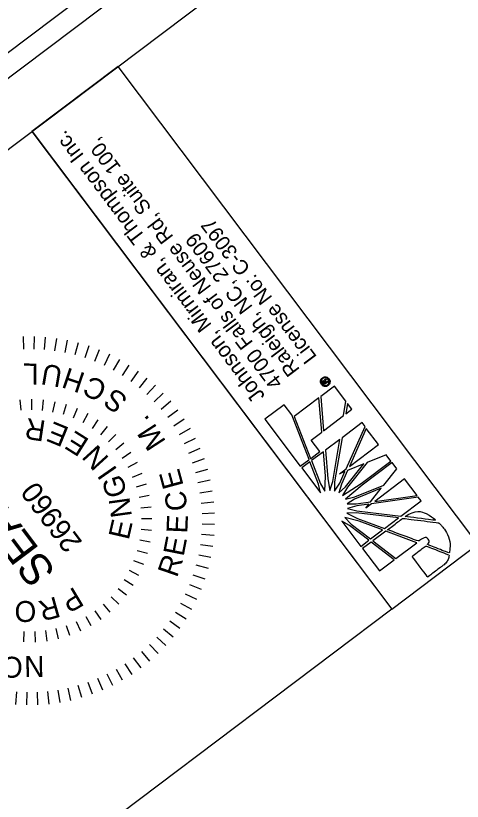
# Model space of a CAD drawing. Extents: x 1263113 to 1265001, y 775064 to 777068.
# Drawn here: x 1263247.8 to 1263346, y 776344.6 to 776517.2 of the extents above; entities that cross this region are included whole.
import ezdxf

# ---------------------------------------------------------------- set-up
doc = ezdxf.new("R2010")
doc.units = 0
for name, color, linetype in [('Default', 7, 'Continuous'), ('Sheet Data Field CELL', 7, 'Continuous'), ('Sheet Plan CELL', 7, 'Continuous'), ('Sheet Plot Border Inside CELL', 7, 'Continuous'), ('Sheet Plot Border Outside CELL', 7, 'Continuous'), ('Sheet Typical CELL', 7, 'Continuous')]:
    doc.layers.add(name, color=color, linetype=linetype)

msp = doc.modelspace()

# ---------------------------------------------------------------- linework, layer by layer
at = {"layer": 'Default'}
for p, q in [((1263249.42, 776446.7), (1263249.53, 776443.95)), ((1263251.87, 776446.73), (1263251.81, 776443.97)), ((1263254.31, 776446.61), (1263254.09, 776443.86)), ((1263256.74, 776446.33), (1263256.35, 776443.6)), ((1263259.15, 776445.92), (1263258.6, 776443.22)), ((1263261.53, 776445.36), (1263260.82, 776442.69)), ((1263263.87, 776444.66), (1263263, 776442.04)), ((1263266.17, 776443.81), (1263265.14, 776441.25)), ((1263268.41, 776442.83), (1263267.23, 776440.34)), ((1263270.59, 776441.71), (1263269.25, 776439.3)), ((1263272.7, 776440.47), (1263271.22, 776438.14)), ((1263274.72, 776439.11), (1263273.1, 776436.86)), ((1263276.66, 776437.61), (1263274.92, 776435.48)), ((1263278.51, 776436.01), (1263276.64, 776433.99)), ((1263280.25, 776434.3), (1263278.26, 776432.39)), ((1263248.69, 776432.83), (1263248.9, 776430.54)), ((1263251.27, 776432.93), (1263251.25, 776430.63)), ((1263253.84, 776432.79), (1263253.61, 776430.5)), ((1263256.39, 776432.4), (1263255.93, 776430.14)), ((1263281.89, 776432.49), (1263279.79, 776430.7)), ((1263258.89, 776431.76), (1263258.22, 776429.56)), ((1263261.32, 776430.88), (1263260.43, 776428.76)), ((1263283.42, 776430.58), (1263281.22, 776428.92)), ((1263263.65, 776429.78), (1263262.56, 776427.75)), ((1263265.86, 776428.45), (1263264.58, 776426.54)), ((1263284.83, 776428.58), (1263282.53, 776427.06)), ((1263267.93, 776426.92), (1263266.48, 776425.14)), ((1263286.12, 776426.5), (1263283.73, 776425.12)), ((1263269.85, 776425.2), (1263268.23, 776423.56)), ((1263287.28, 776424.35), (1263284.81, 776423.11)), ((1263271.59, 776423.3), (1263269.82, 776421.83)), ((1263288.31, 776422.13), (1263285.77, 776421.04)), ((1263273.14, 776421.24), (1263271.24, 776419.94)), ((1263274.48, 776419.03), (1263272.47, 776417.93)), ((1263289.2, 776419.85), (1263286.6, 776418.92)), ((1263273.5, 776415.8), (1263275.62, 776416.7)), ((1263289.95, 776417.52), (1263287.3, 776416.75)), ((1263290.55, 776415.15), (1263287.87, 776414.54)), ((1263276.5, 776414.3), (1263274.31, 776413.6)), ((1263277.16, 776411.8), (1263274.91, 776411.32)), ((1263291.02, 776412.75), (1263288.3, 776412.31)), ((1263291.34, 776410.32), (1263288.6, 776410.05)), ((1263277.58, 776409.25), (1263275.29, 776409)), ((1263277.74, 776406.68), (1263275.44, 776406.64)), ((1263291.52, 776407.89), (1263288.76, 776407.78)), ((1263291.54, 776405.44), (1263288.78, 776405.5)), ((1263277.66, 776404.1), (1263275.37, 776404.29)), ((1263291.42, 776403), (1263288.67, 776403.22)), ((1263277.33, 776401.55), (1263275.07, 776401.95)), ((1263276.75, 776399.04), (1263274.54, 776399.66)), ((1263291.15, 776400.57), (1263288.42, 776400.95)), ((1263290.73, 776398.16), (1263288.03, 776398.71)), ((1263275.94, 776396.59), (1263273.79, 776397.42)), ((1263290.17, 776395.77), (1263287.51, 776396.49)), ((1263274.89, 776394.24), (1263272.83, 776395.27)), ((1263289.47, 776393.43), (1263286.85, 776394.31)), ((1263273.62, 776391.99), (1263271.68, 776393.22)), ((1263272.14, 776389.88), (1263270.32, 776391.29)), ((1263288.63, 776391.14), (1263286.06, 776392.17)), ((1263270.46, 776387.92), (1263268.79, 776389.5)), ((1263287.64, 776388.9), (1263285.15, 776390.08)), ((1263268.6, 776386.13), (1263267.09, 776387.87)), ((1263286.53, 776386.72), (1263284.11, 776388.05)), ((1263266.58, 776384.54), (1263265.24, 776386.41)), ((1263285.29, 776384.61), (1263282.95, 776386.09)), ((1263262.11, 776381.96), (1263261.16, 776384.05)), ((1263264.41, 776383.14), (1263263.26, 776385.13)), ((1263283.92, 776382.59), (1263281.68, 776384.2)), ((1263257.24, 776380.29), (1263256.71, 776382.53)), ((1263259.72, 776381.01), (1263258.97, 776383.18)), ((1263282.43, 776380.65), (1263280.29, 776382.39)), ((1263249.56, 776379.61), (1263249.69, 776381.9)), ((1263252.14, 776379.58), (1263252.05, 776381.88)), ((1263254.7, 776379.81), (1263254.4, 776382.09)), ((1263280.83, 776378.8), (1263278.8, 776380.67)), ((1263279.11, 776377.05), (1263277.2, 776379.04)), ((1263277.3, 776375.41), (1263275.51, 776377.52)), ((1263275.39, 776373.88), (1263273.73, 776376.09)), ((1263271.31, 776371.19), (1263269.93, 776373.58)), ((1263273.39, 776372.47), (1263271.87, 776374.77)), ((1263269.16, 776370.03), (1263267.92, 776372.5)), ((1263264.66, 776368.11), (1263263.73, 776370.71)), ((1263266.94, 776369), (1263265.85, 776371.54)), ((1263247.81, 776365.89), (1263248.03, 776368.64)), ((1263250.26, 776365.77), (1263250.31, 776368.53)), ((1263252.7, 776365.79), (1263252.59, 776368.55)), ((1263255.14, 776365.96), (1263254.86, 776368.71)), ((1263257.56, 776366.28), (1263257.12, 776369.01)), ((1263259.96, 776366.75), (1263259.36, 776369.44)), ((1263262.33, 776367.36), (1263261.57, 776370.01))]:
    msp.add_line(p, q, dxfattribs=at)
at = {"layer": 'Sheet Data Field CELL'}
for p, q in [((1263316.52, 776437.3), (1263316.68, 776437.43)), ((1263316.68, 776437.43), (1263316.52, 776437.3)), ((1263316.68, 776437.43), (1263316.68, 776437.43)), ((1263317.89, 776435.83), (1263314.85, 776433.53)), ((1263315.03, 776436.18), (1263315.19, 776436.3)), ((1263315.19, 776436.3), (1263315.03, 776436.18)), ((1263315.47, 776436.52), (1263315.44, 776436.56)), ((1263315.47, 776436.52), (1263315.62, 776436.62)), ((1263315.62, 776436.62), (1263315.47, 776436.52)), ((1263315.7, 776436.21), (1263315.47, 776436.52)), ((1263315.6, 776436.64), (1263315.62, 776436.62)), ((1263315.62, 776436.62), (1263315.72, 776436.49)), ((1263316.46, 776436.78), (1263315.7, 776436.21)), ((1263315.72, 776436.49), (1263315.9, 776436.62)), ((1263315.79, 776436.76), (1263315.93, 776436.86)), ((1263315.93, 776436.86), (1263315.79, 776436.76)), ((1263315.79, 776436.76), (1263315.79, 776436.77)), ((1263315.9, 776436.62), (1263315.79, 776436.76)), ((1263315.93, 776436.87), (1263315.93, 776436.86)), ((1263315.93, 776436.86), (1263316.03, 776436.72)), ((1263316.03, 776436.72), (1263316.33, 776436.95)), ((1263316.33, 776436.95), (1263316.46, 776436.78)), ((1263316.52, 776437.3), (1263316.51, 776437.31)), ((1263320.41, 776432.5), (1263317.89, 776435.83)), ((1263314.47, 776433.25), (1263309.05, 776429.16)), ((1263315.08, 776425.73), (1263314.47, 776433.25)), ((1263314.85, 776433.53), (1263315.49, 776426.03)), ((1263319.88, 776429.34), (1263320.41, 776432.5)), ((1263306.81, 776431.73), (1263302.58, 776428.54)), ((1263308.47, 776429.53), (1263306.81, 776431.73)), ((1263320.77, 776432.02), (1263320.36, 776429.71)), ((1263320.36, 776429.71), (1263321.73, 776430.75)), ((1263321.73, 776430.75), (1263320.77, 776432.02)), ((1263312.33, 776419.69), (1263308.47, 776429.53)), ((1263309.05, 776429.16), (1263312.62, 776419.91)), ((1263315.49, 776426.03), (1263319.88, 776429.34)), ((1263302.58, 776428.54), (1263310.37, 776418.22)), ((1263323.95, 776427.81), (1263319.54, 776424.49)), ((1263324.6, 776426.95), (1263323.95, 776427.81)), ((1263312.73, 776423.95), (1263315.08, 776425.73)), ((1263320.45, 776417.66), (1263324.6, 776426.95)), ((1263324.88, 776426.52), (1263321.15, 776418.19)), ((1263327.54, 776423.01), (1263324.88, 776426.52)), ((1263314.63, 776421.43), (1263312.73, 776423.95)), ((1263319.03, 776424.1), (1263315.89, 776421.73)), ((1263317.51, 776414.84), (1263319.03, 776424.1)), ((1263319.54, 776424.49), (1263317.92, 776414.81)), ((1263321.15, 776418.19), (1263327.54, 776423.01)), ((1263312.65, 776419.93), (1263314.63, 776421.43)), ((1263315.45, 776421.4), (1263312.82, 776419.47)), ((1263315.92, 776416.06), (1263315.45, 776421.4)), ((1263315.89, 776421.73), (1263316.39, 776415.48)), ((1263329.25, 776420.73), (1263325.08, 776419.07)), ((1263330.28, 776419.37), (1263329.25, 776420.73)), ((1263310.37, 776418.22), (1263312.27, 776419.65)), ((1263312.45, 776419.19), (1263310.69, 776417.85)), ((1263312.27, 776419.65), (1263312.33, 776419.69)), ((1263314.38, 776414.26), (1263312.45, 776419.19)), ((1263312.62, 776419.91), (1263312.65, 776419.93)), ((1263312.82, 776419.47), (1263314.84, 776414.39)), ((1263320.31, 776413.73), (1263324.31, 776418.74)), ((1263324.31, 776418.74), (1263320.74, 776417.28)), ((1263325.08, 776419.07), (1263320.76, 776413.59)), ((1263323.74, 776414.43), (1263330.28, 776419.37)), ((1263330.54, 776419.02), (1263324, 776414.08)), ((1263331.56, 776417.68), (1263330.54, 776419.02)), ((1263310.69, 776417.85), (1263314.77, 776412.39)), ((1263319.01, 776416.57), (1263320.45, 776417.66)), ((1263320.18, 776417.06), (1263319.01, 776416.57)), ((1263319.02, 776414.53), (1263320.18, 776417.06)), ((1263320.74, 776417.28), (1263319.39, 776414.27)), ((1263328.72, 776414.08), (1263331.56, 776417.68)), ((1263315.79, 776412.73), (1263315.92, 776416.06)), ((1263316.39, 776415.48), (1263316.87, 776412.87)), ((1263333.26, 776415.47), (1263326.74, 776410.5)), ((1263336.02, 776411.81), (1263333.26, 776415.47)), ((1263314.77, 776412.39), (1263314.38, 776414.26)), ((1263314.84, 776414.39), (1263315.79, 776412.73)), ((1263316.87, 776412.87), (1263317.51, 776414.84)), ((1263317.92, 776414.81), (1263317.9, 776412.74)), ((1263317.9, 776412.74), (1263319.02, 776414.53)), ((1263319.39, 776414.27), (1263318.86, 776412.38)), ((1263318.86, 776412.38), (1263320.31, 776413.73)), ((1263319.67, 776411.76), (1263323.74, 776414.43)), ((1263320.76, 776413.59), (1263319.67, 776411.76)), ((1263324, 776414.08), (1263320.29, 776410.95)), ((1263328.16, 776413.4), (1263322.3, 776410.98)), ((1263322.36, 776411.46), (1263328.72, 776414.08)), ((1263325.8, 776410.39), (1263328.16, 776413.4)), ((1263326.74, 776410.5), (1263336.02, 776411.81)), ((1263320.29, 776410.95), (1263322.36, 776411.46)), ((1263322.3, 776410.98), (1263320.68, 776409.97)), ((1263320.68, 776409.97), (1263322.66, 776409.94)), ((1263322.66, 776409.94), (1263325.8, 776410.39)), ((1263325.44, 776409.91), (1263322.8, 776409.52)), ((1263326.03, 776409.97), (1263324.74, 776408.99)), ((1263324.74, 776408.99), (1263325.44, 776409.91)), ((1263336.31, 776411.43), (1263326.03, 776409.97)), ((1263332.47, 776407.26), (1263336.92, 776410.62)), ((1263336.92, 776410.62), (1263336.31, 776411.43)), ((1263322.8, 776409.52), (1263320.77, 776408.94)), ((1263320.77, 776408.94), (1263322.76, 776408.39)), ((1263322.76, 776408.39), (1263332.47, 776407.26)), ((1263323.34, 776406.16), (1263320.15, 776406.94)), ((1263320.15, 776406.94), (1263321.56, 776405.49)), ((1263322.65, 776407.98), (1263320.61, 776407.92)), ((1263320.61, 776407.92), (1263322.97, 776406.77)), ((1263331.95, 776406.87), (1263322.65, 776407.98)), ((1263322.97, 776406.77), (1263328.89, 776404.56)), ((1263328.89, 776404.56), (1263331.95, 776406.87)), ((1263321.18, 776405.2), (1263319.49, 776406.14)), ((1263319.49, 776406.14), (1263323.66, 776400.61)), ((1263325.42, 776401.94), (1263321.18, 776405.2)), ((1263321.56, 776405.49), (1263325.8, 776402.23)), ((1263328.46, 776404.23), (1263323.34, 776406.16)), ((1263325.8, 776402.23), (1263328.46, 776404.23)), ((1263329.16, 776403.97), (1263326.32, 776401.82)), ((1263335.98, 776401.4), (1263329.16, 776403.97)), ((1263323.66, 776400.61), (1263325.42, 776401.94)), ((1263325.96, 776401.55), (1263324.07, 776400.12)), ((1263331.03, 776397.67), (1263325.96, 776401.55)), ((1263326.32, 776401.82), (1263331.4, 776397.95)), ((1263331.4, 776397.95), (1263335.98, 776401.4)), ((1263324.07, 776400.12), (1263327.77, 776395.21)), ((1263327.77, 776395.21), (1263331.03, 776397.67))]:
    msp.add_line(p, q, dxfattribs=at)
msp.add_lwpolyline([(1263349.4, 776401.09), (1263270.32, 776506.07), (1263251.38, 776491.8), (1263330.45, 776386.82)], close=True, dxfattribs=at)
for points in [[(1263315.8, 776437.28), (1263315.84, 776437.31), (1263315.86, 776437.33), (1263315.89, 776437.36), (1263315.96, 776437.44), (1263316.07, 776437.28)], [(1263315.49, 776426.03), (1263319.88, 776429.34), (1263320.41, 776432.5), (1263317.89, 776435.83), (1263314.85, 776433.53), (1263315.49, 776426.03), (1263315.49, 776426.03)], [(1263312.62, 776419.91), (1263312.65, 776419.93), (1263314.63, 776421.43), (1263312.73, 776423.95), (1263315.08, 776425.73), (1263314.47, 776433.25), (1263309.05, 776429.16), (1263312.62, 776419.91)], [(1263302.58, 776428.54), (1263310.37, 776418.22), (1263312.27, 776419.65), (1263312.33, 776419.69), (1263308.47, 776429.53), (1263306.81, 776431.73), (1263302.58, 776428.54)], [(1263321.73, 776430.75), (1263321.73, 776430.75), (1263320.77, 776432.02), (1263320.36, 776429.71), (1263321.73, 776430.75)], [(1263317.9, 776412.74), (1263319.02, 776414.53), (1263320.18, 776417.06), (1263319.01, 776416.57), (1263320.45, 776417.66), (1263324.6, 776426.95), (1263323.95, 776427.81), (1263319.54, 776424.49), (1263317.92, 776414.81), (1263317.9, 776412.74)], [(1263327.54, 776423.01), (1263324.88, 776426.52), (1263321.15, 776418.19), (1263327.54, 776423.01)], [(1263316.87, 776412.87), (1263317.51, 776414.84), (1263319.03, 776424.1), (1263315.89, 776421.73), (1263316.39, 776415.48), (1263316.87, 776412.87)], [(1263315.79, 776412.73), (1263315.92, 776416.06), (1263315.45, 776421.4), (1263312.82, 776419.47), (1263314.84, 776414.39), (1263315.79, 776412.73)], [(1263319.67, 776411.76), (1263323.74, 776414.43), (1263330.28, 776419.37), (1263329.25, 776420.73), (1263325.08, 776419.07), (1263320.76, 776413.59), (1263319.67, 776411.76)], [(1263314.38, 776414.26), (1263312.45, 776419.19), (1263310.69, 776417.85), (1263314.77, 776412.39), (1263314.38, 776414.26)], [(1263318.86, 776412.38), (1263320.31, 776413.73), (1263324.31, 776418.74), (1263320.74, 776417.28), (1263319.39, 776414.27), (1263318.86, 776412.38)], [(1263322.36, 776411.46), (1263328.72, 776414.08), (1263331.56, 776417.68), (1263330.54, 776419.02), (1263324, 776414.08), (1263320.29, 776410.95), (1263322.36, 776411.46)], [(1263336.02, 776411.81), (1263333.26, 776415.47), (1263326.74, 776410.5), (1263336.02, 776411.81)], [(1263320.68, 776409.97), (1263322.66, 776409.94), (1263325.8, 776410.39), (1263328.16, 776413.4), (1263322.3, 776410.98), (1263320.68, 776409.97)], [(1263320.77, 776408.94), (1263322.76, 776408.39), (1263332.47, 776407.26), (1263336.92, 776410.62), (1263336.31, 776411.43), (1263326.03, 776409.97), (1263324.74, 776408.99), (1263325.44, 776409.91), (1263322.8, 776409.52), (1263320.77, 776408.94)], [(1263325.8, 776402.23), (1263328.46, 776404.23), (1263323.34, 776406.16), (1263320.15, 776406.94), (1263321.56, 776405.49), (1263325.8, 776402.23)], [(1263328.89, 776404.56), (1263331.95, 776406.87), (1263322.65, 776407.98), (1263320.61, 776407.92), (1263322.97, 776406.77), (1263328.89, 776404.56)], [(1263321.18, 776405.2), (1263319.49, 776406.14), (1263323.66, 776400.61), (1263325.42, 776401.94), (1263321.18, 776405.2)], [(1263335.98, 776401.4), (1263329.16, 776403.97), (1263326.32, 776401.82), (1263331.4, 776397.95), (1263335.98, 776401.4)], [(1263331.03, 776397.67), (1263325.96, 776401.55), (1263324.07, 776400.12), (1263327.77, 776395.21), (1263331.03, 776397.67)]]:
    msp.add_lwpolyline(points, dxfattribs=at)
for points, degree in [([(1263315.03, 776436.18), (1263314.85, 776436.41), (1263314.79, 776436.67), (1263314.82, 776436.96), (1263314.85, 776437.23), (1263314.98, 776437.46), (1263315.21, 776437.64)], 3), ([(1263316.51, 776437.31), (1263316.37, 776437.5), (1263316.19, 776437.61), (1263315.97, 776437.64), (1263315.74, 776437.67), (1263315.52, 776437.61), (1263315.34, 776437.48), (1263315.15, 776437.34), (1263315.04, 776437.14), (1263315.01, 776436.92), (1263314.99, 776436.69), (1263315.04, 776436.49), (1263315.19, 776436.3)], 3), ([(1263316.68, 776437.43), (1263316.85, 776437.2), (1263316.92, 776436.94), (1263316.88, 776436.66), (1263316.84, 776436.37), (1263316.71, 776436.14), (1263316.48, 776435.97), (1263316.24, 776435.79), (1263315.98, 776435.72), (1263315.71, 776435.78), (1263315.43, 776435.82), (1263315.2, 776435.95), (1263315.03, 776436.18)], 3), ([(1263315.21, 776437.64), (1263315.45, 776437.81), (1263315.71, 776437.88), (1263315.99, 776437.85), (1263316.27, 776437.8), (1263316.5, 776437.67), (1263316.68, 776437.43)], 3), ([(1263315.19, 776436.3), (1263315.33, 776436.12), (1263315.51, 776436.01), (1263315.73, 776435.97), (1263315.95, 776435.94), (1263316.17, 776435.99), (1263316.35, 776436.13), (1263316.54, 776436.27), (1263316.65, 776436.46), (1263316.68, 776436.69), (1263316.71, 776436.92), (1263316.66, 776437.12), (1263316.52, 776437.3)], 3), ([(1263315.44, 776436.56), (1263315.29, 776436.76), (1263315.3, 776436.91), (1263315.45, 776437.02), (1263315.51, 776437.07), (1263315.59, 776437.09), (1263315.68, 776437.06)], 3), ([(1263315.79, 776436.77), (1263315.71, 776436.87), (1263315.63, 776436.9), (1263315.57, 776436.86), (1263315.51, 776436.82), (1263315.52, 776436.75), (1263315.6, 776436.64)], 3), ([(1263315.68, 776437.06), (1263315.67, 776437.12), (1263315.71, 776437.2), (1263315.8, 776437.28)], 2), ([(1263316.07, 776437.28), (1263316.05, 776437.23), (1263316.02, 776437.18), (1263315.96, 776437.14), (1263315.9, 776437.09), (1263315.86, 776437.05), (1263315.85, 776437.02)], 3), ([(1263315.85, 776437.02), (1263315.86, 776436.99), (1263315.87, 776436.94), (1263315.93, 776436.87)], 2), ([(1263333.39, 776407.16), (1263333.39, 776407.16), (1263340.23, 776406.31), (1263340.23, 776406.31), (1263338.35, 776407.83), (1263335.71, 776408.76), (1263333.39, 776407.16)], 3), ([(1263338.5, 776402.2), (1263338.72, 776401.91), (1263338.75, 776401.53), (1263338.28, 776401.02), (1263338.28, 776401.02), (1263343.12, 776399.14), (1263343.12, 776399.14), (1263343.44, 776401.09), (1263342.82, 776403.33), (1263341.71, 776404.8), (1263341.42, 776405.18), (1263341.17, 776405.45), (1263340.78, 776405.79), (1263340.78, 776405.79), (1263332.88, 776406.77), (1263332.88, 776406.77), (1263332.88, 776406.77), (1263329.57, 776404.27), (1263329.57, 776404.27), (1263329.57, 776404.27), (1263336.39, 776401.72), (1263336.39, 776401.72), (1263337.63, 776402.65), (1263338.19, 776402.6), (1263338.5, 776402.2)], 3), ([(1263338.5, 776402.2), (1263338.72, 776401.91), (1263338.75, 776401.53), (1263338.28, 776401.02), (1263338.28, 776401.02), (1263343.12, 776399.14), (1263343.12, 776399.14), (1263343.44, 776401.09), (1263342.82, 776403.33), (1263341.71, 776404.8), (1263341.42, 776405.18), (1263341.17, 776405.45), (1263340.78, 776405.79), (1263340.78, 776405.79), (1263332.88, 776406.77), (1263332.88, 776406.77), (1263332.88, 776406.77), (1263329.57, 776404.27), (1263329.57, 776404.27), (1263329.57, 776404.27), (1263336.39, 776401.72), (1263336.39, 776401.72), (1263337.63, 776402.65), (1263338.19, 776402.6), (1263338.5, 776402.2)], 3), ([(1263334.94, 776398.41), (1263334.94, 776398.41), (1263338.37, 776393.86), (1263338.37, 776393.86), (1263338.37, 776393.86), (1263341.21, 776396.01), (1263341.21, 776396.01), (1263341.21, 776396.01), (1263341.51, 776396.23), (1263341.51, 776396.23), (1263342.4, 776396.91), (1263342.89, 776397.73), (1263343.09, 776398.69), (1263343.09, 776398.69), (1263338, 776400.72), (1263337.94, 776400.67), (1263337.94, 776400.67), (1263334.94, 776398.41), (1263334.94, 776398.41)], 3)]:
    msp.add_open_spline(points, degree=degree, dxfattribs=at)
at = {"layer": 'Sheet Plan CELL'}
msp.add_lwpolyline([(1263251.41, 776491.76), (1263330.45, 776386.82), (1263240.62, 776319.15), (1263161.57, 776424.1)], dxfattribs=at)
at = {"layer": 'Sheet Plot Border Inside CELL'}
msp.add_lwpolyline([(1264977.07, 775721.54), (1263974.73, 777052.27), (1263132.03, 776417.56), (1264134.37, 775086.81)], close=True, dxfattribs=at)
at = {"layer": 'Sheet Plot Border Outside CELL'}
msp.add_lwpolyline([(1263113.35, 776409.12), (1264126.21, 775064.39), (1265000.86, 775723.19), (1263988, 777067.91)], close=True, dxfattribs=at)
at = {"layer": 'Sheet Typical CELL'}
msp.add_line((1263141.54, 776409.07), (1263980.25, 777040.79), dxfattribs=at)

# ---------------------------------------------------------------- texts
at = {"layer": 'Default'}
for s, height, rotation, p in [('L', 4.6, 179.1415, (1263252.88, 776440.77)), ('U', 4.6, 170.2588, (1263258.33, 776440.05)), ('H', 4.6, 161.3762, (1263263.33, 776438.57)), ('C', 4.6, 152.5536, (1263268.24, 776436.25)), ('S', 4.6, 143.551, (1263272.72, 776433.19)), ('R', 4.6, 171.4993, (1263254.61, 776428.18)), ('.', 4.6, 130.7667, (1263277.46, 776428.53)), ('E', 4.6, 157.7282, (1263259.8, 776426.6)), ('M', 4.6, 123.0244, (1263280.95, 776423.65)), ('E', 4.6, 147.7423, (1263264.21, 776424.01)), ('N', 4.6, 132.3503, (1263268.52, 776419.98)), ('I', 4.6, 124.7206, (1263270.28, 776417.39)), ('E', 4.6, 105.229, (1263284.76, 776413.97)), ('G', 4.6, 106.6258, (1263272.39, 776412.13)), ('SEAL', 6.899, 126.9344, (1263256.83, 776395.12)), ('26960', 4.596, 126.9344, (1263262.59, 776401.54)), ('C', 4.6, 96.2566, (1263285.55, 776408.61)), ('N', 4.6, 97.8596, (1263273.37, 776407.24)), ('E', 4.6, 77.0045, (1263272.63, 776401.85)), ('E', 4.6, 87.584, (1263285.52, 776403.39)), ('E', 4.6, 78.9412, (1263284.7, 776398.25)), ('R', 4.6, 70.8694, (1263283.24, 776393.59)), ('P', 4.6, 211.0638, (1263260.77, 776391.83)), ('R', 4.6, 195.7675, (1263256.71, 776389.65)), ('O', 4.6, 180.4713, (1263252.31, 776388.62)), ('O', 4.6, 178.6517, (1263249.4, 776376.29)), ('N', 4.6, 180.6111, (1263254.09, 776376.52))]:
    msp.add_text(s, height=height, rotation=rotation, dxfattribs=at).set_placement(p)
at = {"layer": 'Sheet Data Field CELL'}
for s, height, p in [('Johnson, Mirmiran, & Thompson Inc.', 3.3582, (1263302.74, 776433.7)), ('4700 Falls of Neuse Rd, Suite 100, ', 3.2623, (1263306.68, 776436.67)), ('License No: C-3097', 3.2623, (1263314.13, 776442.28)), ('Raleigh, NC, 27609', 3.2623, (1263310.4, 776439.47))]:
    msp.add_text(s, height=height, rotation=126.9874, dxfattribs=at).set_placement(p)

doc.saveas('drawing.dxf')
